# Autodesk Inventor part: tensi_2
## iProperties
Author: MAX
Created: 2002-09
Part Number: tensi_2
Material: Standard
Document SubType Name: Modellieren
Designer: MAX
Control State: 0
Master: False
Checked Out: False
PropertySet Name: Design Tracking Control
Shininess: 20.0
Angle Display Precision: 2
Document Length Units: 11269
Document Angle Units: 11283
Document Time Units: 11279
Document Mass Units: 11290
Document Length Units Precision: 3
Document Angle Units Precision: 2
Compacted: False
PropertySet Name: _Private Model Information
Density: 0.0
Volumn: 0.0
Area: 0.0
PropertySet Name: Model Information
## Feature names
1. Drehung1 [Revolution]
2. Rechteckige Anordnung1 [Rectangular Pattern]
